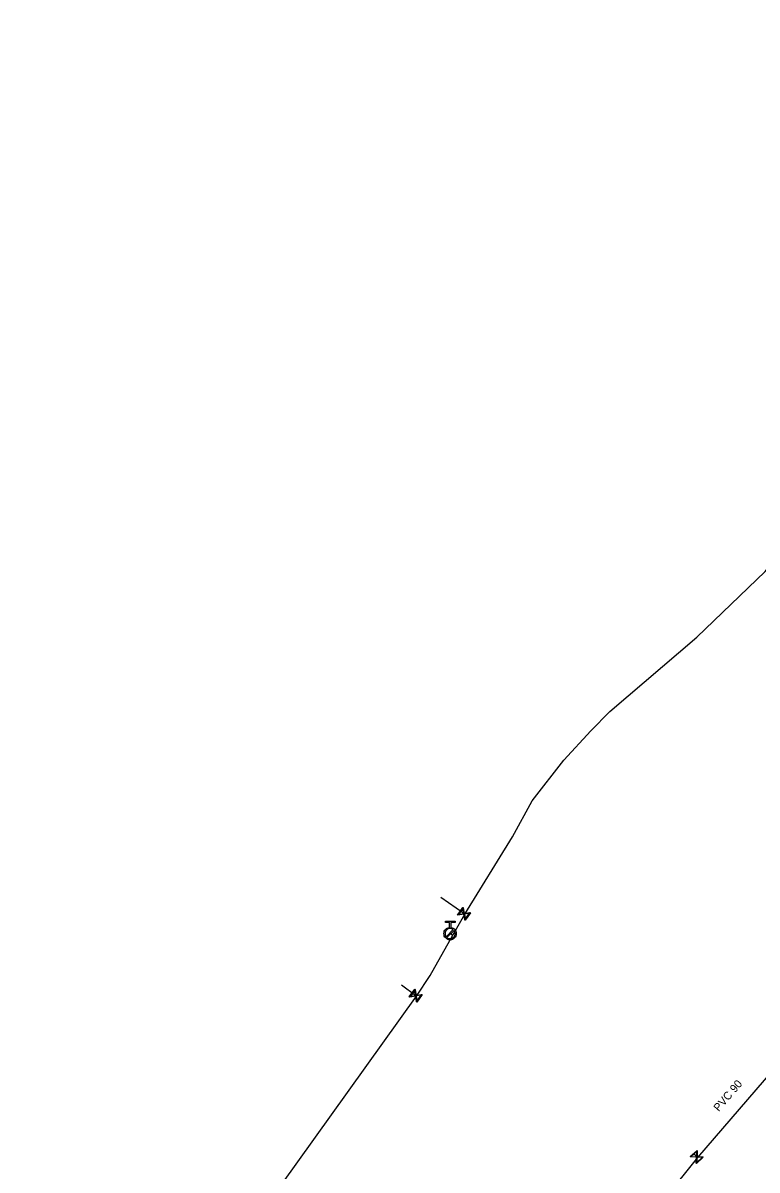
# Model space of a CAD drawing. Extents: x -641905 to -641246, y -1111750 to -1110210.
# Drawn here: x -641664.6 to -641545.3, y -1110592 to -1110405.6 of the extents above; entities that cross this region are included whole.
import ezdxf

# ---------------------------------------------------------------- set-up
doc = ezdxf.new("R2010")
doc.units = 0
for name, color, linetype in [('Default', 7, 'Continuous'), ('VP Hydrant', 7, 'Continuous'), ('VP Přípojka', 7, 'Continuous'), ('VP Řad', 7, 'Continuous'), ('VP Řad - popis', 7, 'Continuous'), ('VP Šoupě', 7, 'Continuous')]:
    doc.layers.add(name, color=color, linetype=linetype)

msp = doc.modelspace()

# ---------------------------------------------------------------- linework, layer by layer
at = {"layer": 'Default'}
for points in [[(-641595.1, -1110552.57), (-641594.74, -1110552.6), (-641594.48, -1110552.86), (-641594.19, -1110553.16), (-641594.19, -1110553.57), (-641594.19, -1110553.99), (-641594.48, -1110554.28), (-641594.78, -1110554.57), (-641595.19, -1110554.57), (-641595.61, -1110554.57), (-641595.9, -1110554.28), (-641596.19, -1110553.98), (-641596.19, -1110553.57), (-641596.19, -1110553.15), (-641595.9, -1110552.86), (-641595.64, -1110552.6), (-641595.28, -1110552.57)], [(-641594.68, -1110552.93), (-641594.9, -1110552.76), (-641595.19, -1110552.76), (-641595.53, -1110552.76), (-641595.77, -1110552.99), (-641596, -1110553.23), (-641596, -1110553.57), (-641596, -1110553.86), (-641595.83, -1110554.08)], [(-641595.7, -1110554.21), (-641595.48, -1110554.38), (-641595.19, -1110554.38), (-641594.86, -1110554.38), (-641594.62, -1110554.14), (-641594.38, -1110553.91), (-641594.38, -1110553.57), (-641594.38, -1110553.28), (-641594.55, -1110553.06)]]:
    msp.add_open_spline(points, degree=3, dxfattribs=at)
at = {"layer": 'VP Hydrant'}
for points in [[(-641595.28, -1110552.57), (-641595.28, -1110551.75), (-641595.97, -1110551.75), (-641595.97, -1110551.57), (-641594.4, -1110551.57), (-641594.4, -1110551.76), (-641595.09, -1110551.75), (-641595.1, -1110552.57)], [(-641595.83, -1110554.08), (-641594.68, -1110552.93)], [(-641594.55, -1110553.06), (-641595.7, -1110554.21)]]:
    msp.add_lwpolyline(points, dxfattribs=at)
at = {"layer": 'VP Přípojka'}
for points in [[(-641592.83, -1110550.42), (-641592.99, -1110550.32), (-641596.72, -1110547.73)], [(-641594.73, -1110553.8), (-641594.89, -1110553.77), (-641595.19, -1110553.57)], [(-641600.63, -1110563.76), (-641600.77, -1110563.66), (-641603.09, -1110561.96)], [(-641555.14, -1110589.85), (-641555.62, -1110589.32)], [(-641555.14, -1110589.85), (-641554.97, -1110589.92)]]:
    msp.add_lwpolyline(points, dxfattribs=at)
at = {"layer": 'VP Řad'}
for points in [[(-641664.58, -1110640.46), (-641633.71, -1110609.9), (-641600.63, -1110563.76), (-641598.45, -1110560.36), (-641594.73, -1110553.8), (-641592.83, -1110550.42), (-641585.04, -1110537.85), (-641581.85, -1110531.99), (-641576.72, -1110525.41), (-641572.32, -1110520.62), (-641569.27, -1110517.47), (-641555.1, -1110505.43), (-641544.01, -1110494.76), (-641533.36, -1110480.93), (-641531.9, -1110478.13), (-641529.81, -1110469.31), (-641527.31, -1110459.48), (-641524.97, -1110448.07), (-641523.07, -1110437.29), (-641521.61, -1110424.89), (-641523.18, -1110409.24), (-641525.76, -1110394.87), (-641527.66, -1110384.33)], [(-641606.72, -1110649.72), (-641606.63, -1110649.64), (-641606.61, -1110649.53), (-641606.49, -1110649.41), (-641597.96, -1110641.06), (-641597.05, -1110639.76), (-641582.85, -1110623.35), (-641570.58, -1110609.06), (-641560.21, -1110596.51), (-641554.97, -1110589.92), (-641538.7, -1110571.11), (-641533.56, -1110565.36), (-641525.73, -1110556.61), (-641525.22, -1110556.04), (-641523.66, -1110554.29), (-641522.92, -1110554.82), (-641518.3, -1110558.16), (-641514.31, -1110561.04), (-641510.94, -1110563.03), (-641509.87, -1110563.7)]]:
    msp.add_lwpolyline(points, dxfattribs=at)
at = {"layer": 'VP Šoupě'}
for points in [[(-641591.89, -1110550.17), (-641592.74, -1110551.4), (-641592.8, -1110551.37), (-641592.82, -1110551.24), (-641592.97, -1110550.41), (-641593.92, -1110550.59), (-641593.97, -1110550.55), (-641593.12, -1110549.32), (-641593.06, -1110549.35), (-641592.89, -1110550.31), (-641592.07, -1110550.16), (-641591.94, -1110550.13), (-641591.89, -1110550.17)], [(-641593.81, -1110550.48), (-641592.98, -1110550.33), (-641593.13, -1110549.5), (-641593.81, -1110550.48)], [(-641592.05, -1110550.25), (-641592.88, -1110550.4), (-641592.73, -1110551.22), (-641592.05, -1110550.25)], [(-641599.72, -1110563.49), (-641600.6, -1110564.71), (-641600.65, -1110564.67), (-641600.67, -1110564.54), (-641600.8, -1110563.71), (-641601.76, -1110563.87), (-641601.82, -1110563.83), (-641600.94, -1110562.61), (-641600.89, -1110562.65), (-641600.73, -1110563.61), (-641599.9, -1110563.47), (-641599.78, -1110563.45), (-641599.72, -1110563.49)], [(-641601.65, -1110563.77), (-641600.82, -1110563.63), (-641600.96, -1110562.8), (-641601.65, -1110563.77)], [(-641599.89, -1110563.56), (-641600.72, -1110563.7), (-641600.58, -1110564.52), (-641599.89, -1110563.56)], [(-641554.08, -1110589.9), (-641555.19, -1110590.91), (-641555.23, -1110590.86), (-641555.22, -1110590.73), (-641555.19, -1110589.89), (-641556.16, -1110589.85), (-641556.2, -1110589.8), (-641555.09, -1110588.79), (-641555.05, -1110588.84), (-641555.09, -1110589.81), (-641554.25, -1110589.85), (-641554.12, -1110589.85), (-641554.08, -1110589.9)], [(-641556.02, -1110589.77), (-641555.18, -1110589.81), (-641555.14, -1110588.97), (-641556.02, -1110589.77)], [(-641554.26, -1110589.94), (-641555.1, -1110589.9), (-641555.14, -1110590.73), (-641554.26, -1110589.94)]]:
    msp.add_lwpolyline(points, dxfattribs=at)

# ---------------------------------------------------------------- texts
at = {"layer": 'VP Řad - popis'}
msp.add_text('PVC 90', height=1.3, rotation=49.1413, dxfattribs=at).set_placement((-641551.56, -1110582.57))

doc.saveas('drawing.dxf')
